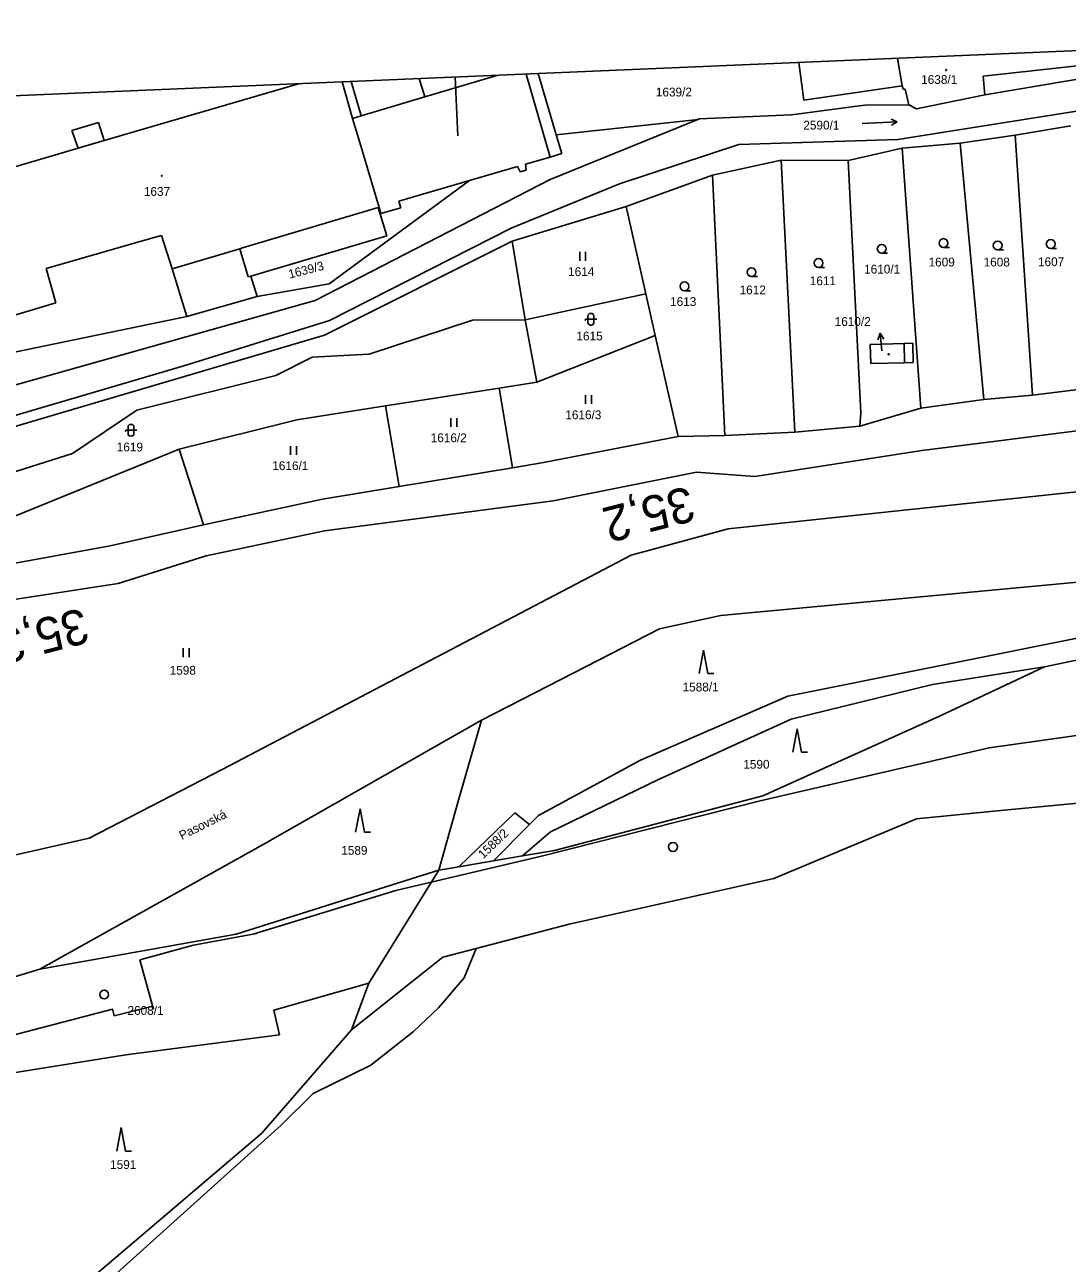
# Model space of a CAD drawing. Extents: x -806456 to -805395, y -1150847 to -1150506.
# Drawn here: x -806109.9 to -805932.5, y -1150734.5 to -1150523.9 of the extents above; entities that cross this region are included whole.
import ezdxf

# ---------------------------------------------------------------- set-up
doc = ezdxf.new("R2010")
doc.units = 0
for name, color, linetype in [('Default', 7, 'Continuous'), ('formát', 7, 'Continuous'), ('kilometráž - vrstava 7', 7, 'Continuous'), ('kn_celek - Cisla parcel pomocna', 7, 'Continuous'), ('kn_celek - Cisla pozemkovych parcel', 7, 'Continuous'), ('kn_celek - Cisla stavebnich parcel', 7, 'Continuous'), ('kn_celek - Dalsi prvky mapy popis', 7, 'Continuous'), ('kn_celek - Hranice parcel', 7, 'Continuous'), ('kn_celek - Vnitrni kresby', 7, 'Continuous'), ('kn_celek - Znacky budov', 7, 'Continuous'), ('kn_celek - Znacky kultur', 7, 'Continuous'), ('plochy - SZDC', 7, 'Continuous'), ('PSR_C2_2_trasa_Vimperk - Kabelová trasa', 7, 'Continuous')]:
    doc.layers.add(name, color=color, linetype=linetype)

# ---------------------------------------------------------------- blocks, each defined once
blk = doc.blocks.new('308')
at = {"layer": 'Default'}
for p, q in [((-7.5, 0.2), (0, 40.2)), ((0, 40.2), (7.5, 0.2)), ((7.5, 0.2), (17.5, 0.2))]:
    blk.add_line(p, q, dxfattribs=at)
blk = doc.blocks.new('306')
at = {"layer": 'Default'}
for p, q in [((-5.2, 0), (-5.2, 15)), ((4.8, 0), (4.8, 15))]:
    blk.add_line(p, q, dxfattribs=at)
blk = doc.blocks.new('304')
at = {"layer": 'Default'}
blk.add_line((-0.1, 0), (9.9, 0), dxfattribs=at)
blk.add_circle((-0.1, 7.5), 7.5, dxfattribs=at)
blk = doc.blocks.new('316')
at = {"layer": 'Default'}
for p, q in [((-8.3, 10), (-10, 8.1)), ((-5, 10), (-8.3, 10)), ((-5, 15.5), (-5, 4.5)), ((-5, 10), (5, 10)), ((0.5, 20), (-0.5, 20)), ((-0.5, 0), (0.5, 0)), ((5, 4.5), (5, 15.5)), ((10, 10), (5, 10))]:
    blk.add_line(p, q, dxfattribs=at)
for centre, start, end in [((-0.5, 15.5), 90, 180), ((-0.5, 4.5), 180, 270), ((0.5, 15.5), 0, 90), ((0.5, 4.5), 270, 0)]:
    blk.add_arc(centre, 4.5, start, end, dxfattribs=at)
blk = doc.blocks.new('402')
at = {"layer": 'Default'}
for p, q in [((-0.8, 0.8), (0.7, 0.8)), ((-0.8, 0.8), (-0.8, -0.7)), ((0.7, 0.8), (0.7, -0.7)), ((0.7, -0.7), (-0.8, -0.7))]:
    blk.add_line(p, q, dxfattribs=at)
blk = doc.blocks.new('Z61')
at = {"layer": 'Default'}
for p, q in [((0, 0), (30, 0)), ((30, 0), (19.2, 5.3)), ((30, 0), (19.2, -5.3))]:
    blk.add_line(p, q, dxfattribs=at)
blk = doc.blocks.new('802')
at = {"layer": 'Default'}
for p, q in [((-30, 0), (30, 0)), ((20, 5), (30, 0)), ((30, 0), (20, -5))]:
    blk.add_line(p, q, dxfattribs=at)

msp = doc.modelspace()

# ---------------------------------------------------------------- linework, layer by layer
at = {"layer": 'formát'}
for p, q in [((-805826.83, -1150523.88), (-806456.26, -1150550.6)), ((-806036.64, -1150532.78), (-806036.21, -1150542.77))]:
    msp.add_line(p, q, dxfattribs=at)
at = {"layer": 'kilometráž - vrstava 7'}
for centre in [(-805999.58, -1150663.73), (-806096.38, -1150688.84)]:
    msp.add_circle(centre, 0.75, dxfattribs=at)
at = {"layer": 'kn_celek - Hranice parcel'}
for p, q in [((-805977.29, -1150536.72), (-805978.14, -1150530.3)), ((-805946.48, -1150535.78), (-805914.7, -1150530.39)), ((-806041.82, -1150536.14), (-806029.54, -1150532.48)), ((-806022.54, -1150532.18), (-806019.46, -1150542.59)), ((-806063.28, -1150533.91), (-806096.37, -1150543.56)), ((-806042.75, -1150533.04), (-806041.82, -1150536.14)), ((-805977.29, -1150536.72), (-805960.6, -1150534.25)), ((-805960.6, -1150534.25), (-805960.43, -1150534.83)), ((-805960.43, -1150534.83), (-805960.05, -1150534.84)), ((-805960.05, -1150534.84), (-805959.42, -1150537.5)), ((-805958.14, -1150538.16), (-805946.48, -1150535.78)), ((-805978.52, -1150539.1), (-805967.87, -1150537.65)), ((-805967.87, -1150537.65), (-805966.95, -1150537.56)), ((-805966.95, -1150537.56), (-805959.42, -1150537.5)), ((-805959.42, -1150537.5), (-805958.14, -1150538.16)), ((-806097.35, -1150540.5), (-806101.91, -1150541.84)), ((-806096.37, -1150543.56), (-806097.35, -1150540.5)), ((-805995.79, -1150540.03), (-806019.46, -1150542.59)), ((-805995.08, -1150539.89), (-805995.79, -1150540.03)), ((-805995.08, -1150539.89), (-805979.47, -1150539.21)), ((-805979.47, -1150539.21), (-805978.52, -1150539.1)), ((-805941.33, -1150542.63), (-805931.86, -1150541.09)), ((-806100.8, -1150544.86), (-806101.91, -1150541.84)), ((-806019.46, -1150542.59), (-806018.51, -1150545.8)), ((-805950.71, -1150544.04), (-805941.33, -1150542.63)), ((-805941.33, -1150542.63), (-805938.4, -1150586.88)), ((-806114.14, -1150548.78), (-806100.8, -1150544.86)), ((-805969.76, -1150546.96), (-805960.55, -1150544.86)), ((-805960.55, -1150544.86), (-805950.71, -1150544.04)), ((-805960.55, -1150544.86), (-805957.42, -1150589.07)), ((-805950.71, -1150544.04), (-805946.65, -1150587.64)), ((-806020.5, -1150546.37), (-806024.69, -1150547.58)), ((-806018.51, -1150545.8), (-806020.5, -1150546.37)), ((-805992.86, -1150549.46), (-805981.18, -1150546.9)), ((-805981.18, -1150546.9), (-805969.76, -1150546.96)), ((-805981.18, -1150546.9), (-805978.86, -1150593.2)), ((-805967.59, -1150589.89), (-805969.76, -1150546.96)), ((-806026.01, -1150547.98), (-806034.23, -1150550.39)), ((-806025.58, -1150548.89), (-806026.01, -1150547.98)), ((-806024.56, -1150548.59), (-806025.58, -1150548.89)), ((-806024.69, -1150547.58), (-806024.56, -1150548.59)), ((-806007.57, -1150554.77), (-805992.86, -1150549.46)), ((-805992.86, -1150549.46), (-805990.76, -1150593.74)), ((-806058.11, -1150567.96), (-806034.23, -1150550.39)), ((-806034.23, -1150550.39), (-806046.24, -1150553.91)), ((-806049.73, -1150554.98), (-806049.6, -1150554.94)), ((-806049.73, -1150554.98), (-806048.3, -1150559.8)), ((-806049.6, -1150554.94), (-806049.29, -1150556)), ((-806049.29, -1150556), (-806045.9, -1150555.02)), ((-806045.9, -1150555.02), (-806046.24, -1150553.91)), ((-806007.57, -1150554.77), (-806026.96, -1150560.67)), ((-806004.21, -1150569.63), (-806007.57, -1150554.77)), ((-806088.1, -1150560.13), (-806086.61, -1150559.7)), ((-806086.61, -1150559.7), (-806084.82, -1150565.38)), ((-806071.41, -1150566.62), (-806048.3, -1150559.8)), ((-806106.27, -1150565.35), (-806088.1, -1150560.13)), ((-806058.91, -1150576.7), (-806026.96, -1150560.67)), ((-806026.96, -1150560.67), (-806024.74, -1150574.06)), ((-806104.61, -1150571.2), (-806106.27, -1150565.35)), ((-806084.82, -1150565.38), (-806082.33, -1150573.48)), ((-806071.41, -1150566.62), (-806070.37, -1150570.09)), ((-806070.37, -1150570.09), (-806058.11, -1150567.96)), ((-806082.33, -1150573.48), (-806070.37, -1150570.09)), ((-806024.74, -1150574.06), (-806004.21, -1150569.63)), ((-806002.61, -1150576.71), (-806004.21, -1150569.63)), ((-806119.82, -1150575.72), (-806104.61, -1150571.2)), ((-806140.34, -1150585.49), (-806082.33, -1150573.48)), ((-806033.68, -1150574.14), (-806051.26, -1150579.89)), ((-806024.74, -1150574.06), (-806033.68, -1150574.14)), ((-806024.74, -1150574.06), (-806022.77, -1150584.69)), ((-806115.37, -1150593.3), (-806058.91, -1150576.7)), ((-806022.77, -1150584.69), (-806002.61, -1150576.71)), ((-805998.72, -1150593.9), (-806002.61, -1150576.71)), ((-805966.01, -1150578.24), (-805960.25, -1150578.09)), ((-805965.92, -1150581.52), (-805966.01, -1150578.24)), ((-805960.25, -1150578.09), (-805958.74, -1150578.04)), ((-805958.74, -1150578.04), (-805958.71, -1150581.32)), ((-806060.99, -1150580.41), (-806067.16, -1150583.54)), ((-806051.26, -1150579.89), (-806060.99, -1150580.41)), ((-805960.16, -1150581.36), (-805965.92, -1150581.52)), ((-805958.71, -1150581.32), (-805960.16, -1150581.36)), ((-806067.16, -1150583.54), (-806090.84, -1150589.43)), ((-806029.15, -1150585.69), (-806022.77, -1150584.69)), ((-806048.5, -1150588.71), (-806029.15, -1150585.69)), ((-806029.15, -1150585.69), (-806027.42, -1150596.15)), ((-805938.4, -1150586.88), (-805946.65, -1150587.64)), ((-805927.83, -1150585.59), (-805938.4, -1150586.88)), ((-806090.84, -1150589.43), (-806101.77, -1150596.83)), ((-806063.57, -1150591.06), (-806048.5, -1150588.71)), ((-806046.18, -1150602.41), (-806048.5, -1150588.71)), ((-805957.42, -1150589.07), (-805967.77, -1150592.14)), ((-805946.65, -1150587.64), (-805957.42, -1150589.07)), ((-806083.6, -1150596.08), (-806063.57, -1150591.06)), ((-805967.77, -1150592.14), (-805967.59, -1150589.89)), ((-805990.76, -1150593.74), (-805998.72, -1150593.9)), ((-805978.86, -1150593.2), (-805990.76, -1150593.74)), ((-805978.86, -1150593.2), (-805967.77, -1150592.14)), ((-805930.82, -1150592.93), (-805944.13, -1150594.65)), ((-806021.64, -1150598.35), (-805998.72, -1150593.9)), ((-805944.13, -1150594.65), (-805957.21, -1150596.28)), ((-806118.38, -1150602.03), (-806101.77, -1150596.83)), ((-806116.57, -1150609.49), (-806083.6, -1150596.08)), ((-806083.6, -1150596.08), (-806079.49, -1150608.96)), ((-806027.42, -1150596.15), (-806026.91, -1150599.22)), ((-805957.21, -1150596.28), (-805985.67, -1150600.72)), ((-806026.91, -1150599.22), (-806046.18, -1150602.41)), ((-806026.91, -1150599.22), (-806021.64, -1150598.35)), ((-805995.57, -1150599.97), (-806019.97, -1150604.84)), ((-805985.67, -1150600.72), (-805995.57, -1150599.97)), ((-805990.21, -1150609.59), (-805890.43, -1150599.04)), ((-806059.25, -1150604.57), (-806046.18, -1150602.41)), ((-806079.49, -1150608.96), (-806059.25, -1150604.57)), ((-806019.97, -1150604.84), (-806058.89, -1150609.96)), ((-806095.36, -1150612.49), (-806079.49, -1150608.96)), ((-806058.89, -1150609.96), (-806079.02, -1150614.23)), ((-805990.21, -1150609.59), (-806006.71, -1150614.09)), ((-806120.89, -1150617.2), (-806095.36, -1150612.49)), ((-806094.01, -1150618.9), (-806079.02, -1150614.23)), ((-806006.71, -1150614.09), (-806076.28, -1150650.56)), ((-805991.42, -1150624.34), (-805889.59, -1150614.88)), ((-806094.01, -1150618.9), (-806120.22, -1150622.93)), ((-805955.67, -1150633.22), (-805906.01, -1150623.2)), ((-806001.85, -1150626.61), (-805991.42, -1150624.34)), ((-806018.57, -1150635.19), (-806001.85, -1150626.61)), ((-805936.34, -1150633.1), (-805905.92, -1150626.68)), ((-805955.67, -1150633.22), (-805980.05, -1150638.11)), ((-805955.42, -1150636.11), (-805936.34, -1150633.1)), ((-805954.21, -1150641.47), (-805936.34, -1150633.1)), ((-806032.16, -1150642.17), (-806018.57, -1150635.19)), ((-805979.44, -1150641.98), (-805955.42, -1150636.11)), ((-806005.08, -1150648.95), (-805980.05, -1150638.11)), ((-806069.3, -1150663.29), (-806032.16, -1150642.17)), ((-806036.17, -1150656.19), (-806032.16, -1150642.17)), ((-806002.04, -1150652.23), (-805979.44, -1150641.98)), ((-805984.31, -1150655.05), (-805954.21, -1150641.47)), ((-806076.28, -1150650.56), (-806098.93, -1150662.23)), ((-806022.45, -1150658.38), (-806005.08, -1150648.95)), ((-806020.42, -1150661.14), (-806002.04, -1150652.23)), ((-805944.43, -1150657.58), (-805909.49, -1150654.26)), ((-806039.45, -1150667.69), (-806036.17, -1150656.19)), ((-806019.74, -1150664.32), (-805984.31, -1150655.05)), ((-806026.5, -1150657.92), (-806036.02, -1150667.1)), ((-806023.99, -1150659.92), (-806026.5, -1150657.92)), ((-806023.99, -1150659.92), (-806022.45, -1150658.38)), ((-805982.42, -1150669.1), (-805958.14, -1150658.97)), ((-805958.14, -1150658.97), (-805944.43, -1150657.58)), ((-806030.13, -1150666.09), (-806023.99, -1150659.92)), ((-806020.42, -1150661.14), (-806025.19, -1150665.25)), ((-806098.93, -1150662.23), (-806129.77, -1150669.25)), ((-806107.35, -1150684.54), (-806069.3, -1150663.29)), ((-806030.13, -1150666.09), (-806025.19, -1150665.25)), ((-806025.19, -1150665.25), (-806019.74, -1150664.32)), ((-806039.45, -1150667.69), (-806036.02, -1150667.1)), ((-806036.02, -1150667.1), (-806030.13, -1150666.09)), ((-806073.91, -1150678.57), (-806043.04, -1150668.82)), ((-806051.33, -1150686.88), (-806039.45, -1150667.69)), ((-806043.04, -1150668.82), (-806039.45, -1150667.69)), ((-806017.22, -1150676.88), (-805982.42, -1150669.1)), ((-806033.08, -1150681), (-806017.22, -1150676.88)), ((-806096.14, -1150682.54), (-806073.91, -1150678.57)), ((-806038.72, -1150682.46), (-806033.08, -1150681)), ((-806035.11, -1150686.02), (-806033.08, -1150681)), ((-806107.35, -1150684.54), (-806096.14, -1150682.54)), ((-806054.27, -1150694.84), (-806038.72, -1150682.46)), ((-806152.11, -1150697.83), (-806107.35, -1150684.54)), ((-806035.11, -1150686.02), (-806039.5, -1150691.07)), ((-806067.49, -1150691.49), (-806051.33, -1150686.88)), ((-806051.33, -1150686.88), (-806054.27, -1150694.84)), ((-806066.55, -1150695.68), (-806067.49, -1150691.49)), ((-806039.5, -1150691.07), (-806043.71, -1150695.1)), ((-806054.27, -1150694.84), (-806069.54, -1150712.39)), ((-806092.7, -1150699.08), (-806066.55, -1150695.68)), ((-806043.71, -1150695.1), (-806050.99, -1150700.84)), ((-806114.99, -1150702.66), (-806092.7, -1150699.08)), ((-806050.99, -1150700.84), (-806060.8, -1150705.65)), ((-806060.8, -1150705.65), (-806066.25, -1150711.08)), ((-806066.25, -1150711.08), (-806109.37, -1150749.85)), ((-806069.54, -1150712.39), (-806118.66, -1150754.19))]:
    msp.add_line(p, q, dxfattribs=at)
at = {"layer": 'kn_celek - Vnitrni kresby'}
for p, q in [((-805961.39, -1150529.59), (-805960.6, -1150534.25)), ((-805946.77, -1150532.62), (-805914.93, -1150529.1)), ((-806024.59, -1150532.27), (-806020.5, -1150546.37)), ((-805946.48, -1150535.78), (-805946.77, -1150532.62)), ((-806055.88, -1150533.6), (-806054.09, -1150539.83)), ((-806052.65, -1150539.37), (-806054.35, -1150533.53)), ((-806052.65, -1150539.37), (-806041.82, -1150536.14)), ((-805913.56, -1150535.79), (-805961.29, -1150543.38)), ((-806054.09, -1150539.83), (-806052.65, -1150539.37)), ((-806054.09, -1150539.83), (-806052.86, -1150543.93)), ((-805995.08, -1150539.89), (-806020.46, -1150550.22)), ((-806096.37, -1150543.56), (-806100.8, -1150544.86)), ((-806052.86, -1150543.93), (-806049.6, -1150554.94)), ((-805988.36, -1150544.24), (-806008.67, -1150550.93)), ((-805961.29, -1150543.38), (-805988.36, -1150544.24)), ((-806020.46, -1150550.22), (-806060.49, -1150570.78)), ((-806027.11, -1150558.49), (-806008.67, -1150550.93)), ((-806072.85, -1150561.83), (-806049.73, -1150554.98)), ((-806058.01, -1150574.18), (-806027.11, -1150558.49)), ((-806084.82, -1150565.38), (-806073.32, -1150561.97)), ((-806073.32, -1150561.97), (-806072.85, -1150561.83)), ((-806073.32, -1150561.97), (-806071.89, -1150566.76)), ((-806071.89, -1150566.76), (-806071.41, -1150566.62)), ((-806060.49, -1150570.78), (-806120.54, -1150587.67)), ((-806082.8, -1150581.88), (-806058.01, -1150574.18)), ((-805960.25, -1150578.09), (-805960.16, -1150581.36)), ((-806118.66, -1150592.4), (-806082.8, -1150581.88))]:
    msp.add_line(p, q, dxfattribs=at)
at = {"layer": 'plochy - SZDC'}
for p, q in [((-805905.92, -1150626.68), (-805936.34, -1150633.1)), ((-805936.34, -1150633.1), (-805954.21, -1150641.47)), ((-805954.21, -1150641.47), (-805984.31, -1150655.05)), ((-805944.43, -1150657.58), (-805909.49, -1150654.26)), ((-805984.31, -1150655.05), (-806019.74, -1150664.32)), ((-805982.42, -1150669.1), (-805958.14, -1150658.97)), ((-805958.14, -1150658.97), (-805944.43, -1150657.58)), ((-806025.19, -1150665.25), (-806030.13, -1150666.09)), ((-806019.74, -1150664.32), (-806025.19, -1150665.25)), ((-806036.02, -1150667.1), (-806039.45, -1150667.69)), ((-806030.13, -1150666.09), (-806036.02, -1150667.1)), ((-806043.04, -1150668.82), (-806073.91, -1150678.57)), ((-806051.33, -1150686.88), (-806039.45, -1150667.69)), ((-806039.45, -1150667.69), (-806051.33, -1150686.88)), ((-806039.45, -1150667.69), (-806043.04, -1150668.82)), ((-806017.22, -1150676.88), (-805982.42, -1150669.1)), ((-806033.08, -1150681), (-806017.22, -1150676.88)), ((-806073.91, -1150678.57), (-806096.14, -1150682.54)), ((-806038.72, -1150682.46), (-806033.08, -1150681)), ((-806096.14, -1150682.54), (-806107.35, -1150684.54)), ((-806054.27, -1150694.84), (-806038.72, -1150682.46)), ((-806107.35, -1150684.54), (-806152.11, -1150697.83)), ((-806067.49, -1150691.49), (-806051.33, -1150686.88)), ((-806051.33, -1150686.88), (-806054.27, -1150694.84)), ((-806066.55, -1150695.68), (-806067.49, -1150691.49)), ((-806092.7, -1150699.08), (-806066.55, -1150695.68)), ((-806114.99, -1150702.66), (-806092.7, -1150699.08))]:
    msp.add_line(p, q, dxfattribs=at)
at = {"layer": 'PSR_C2_2_trasa_Vimperk - Kabelová trasa'}
for p, q in [((-805925.76, -1150644.05), (-805945.75, -1150646.88)), ((-805984.72, -1150655.91), (-805945.75, -1150646.88)), ((-806021.98, -1150665.32), (-805984.72, -1150655.91)), ((-806088.19, -1150690.53), (-806090.32, -1150682.96)), ((-806088.19, -1150690.53), (-806087.98, -1150691.34))]:
    msp.add_line(p, q, dxfattribs=at)
for points in [[(-806070.84, -1150678.49), (-806046.76, -1150671.15), (-806021.98, -1150665.32)], [(-806090.32, -1150682.96), (-806081.2, -1150680.45), (-806070.48, -1150678.43)], [(-806165.37, -1150711.96), (-806160.98, -1150708.44), (-806114.54, -1150696.43), (-806094.98, -1150691.3), (-806094.7, -1150692.45)], [(-806094.7, -1150692.45), (-806088.12, -1150690.8)]]:
    msp.add_lwpolyline(points, dxfattribs=at)

# ---------------------------------------------------------------- block references
at = {"layer": 'kn_celek - Cisla parcel pomocna', "xscale": 0.1, "yscale": 0.10000000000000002, "rotation": 95.19435000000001}
msp.add_blockref('Z61', (-805964.02, -1150579.33), dxfattribs=at)
at = {"layer": 'kn_celek - Znacky budov', "xscale": 0.1, "yscale": 0.10000000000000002}
for p in [(-805953.08, -1150531.57), (-806086.56, -1150549.58), (-805962.87, -1150579.93)]:
    msp.add_blockref('402', p, dxfattribs=at)
at = {"layer": 'kn_celek - Znacky kultur', "xscale": 0.10000000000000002, "yscale": 0.10000000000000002, "rotation": 2.8179328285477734}
msp.add_blockref('802', (-805964.41, -1150540.55), dxfattribs=at)
at = {"layer": 'kn_celek - Znacky kultur', "xscale": 0.1, "yscale": 0.10000000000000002}
for name, p in [('304', (-805964.04, -1150562.74)), ('304', (-805953.52, -1150561.76)), ('304', (-805944.31, -1150562.17)), ('304', (-805935.28, -1150561.91)), ('306', (-806014.93, -1150564.02)), ('304', (-805974.79, -1150565.15)), ('304', (-805986.2, -1150566.71)), ('304', (-805997.61, -1150569.12)), ('316', (-806013.55, -1150574.97)), ('306', (-806013.94, -1150588.37)), ('306', (-806036.85, -1150592.28)), ('316', (-806091.82, -1150593.85)), ('306', (-806064.13, -1150597.03)), ('306', (-806082.42, -1150631.42)), ('308', (-805994.37, -1150634.26)), ('308', (-805978.44, -1150647.65)), ('308', (-806052.83, -1150661.26)), ('308', (-806093.5, -1150715.5))]:
    msp.add_blockref(name, p, dxfattribs=at)

# ---------------------------------------------------------------- texts
at = {"layer": 'kilometráž - vrstava 7'}
for s, p in [('35,2', (-805996.87, -1150602.28)), ('35,3', (-806100.01, -1150623))]:
    msp.add_text(s, height=6, rotation=194.6315, dxfattribs=at).set_placement(p)
at = {"layer": 'kn_celek - Cisla parcel pomocna'}
msp.add_text('1610/2', height=1.5, dxfattribs=at).set_placement((-805972.06, -1150575.1))
at = {"layer": 'kn_celek - Cisla pozemkovych parcel'}
for s, p in [('1639/2', (-806002.49, -1150536.07)), ('2590/1', (-805977.39, -1150541.7)), ('1609', (-805956.08, -1150564.99)), ('1608', (-805946.71, -1150564.99)), ('1607', (-805937.46, -1150564.94)), ('1614', (-806017.42, -1150566.62)), ('1610/1', (-805967.05, -1150566.19)), ('1612', (-805988.24, -1150569.73)), ('1611', (-805976.29, -1150568.17)), ('1613', (-806000.07, -1150571.72)), ('1615', (-806016.01, -1150577.57)), ('1616/3', (-806017.9, -1150590.97)), ('1616/2', (-806040.81, -1150594.88)), ('1619', (-806094.24, -1150596.45)), ('1616/1', (-806067.77, -1150599.63)), ('1598', (-806085.23, -1150634.43)), ('1588/1', (-805997.94, -1150637.28)), ('1590', (-805987.61, -1150650.42)), ('1589', (-806056.03, -1150665.06)), ('2608/1', (-806092.41, -1150692.29)), ('1591', (-806095.37, -1150718.51))]:
    msp.add_text(s, height=1.5, dxfattribs=at).set_placement(p)
for s, rotation, p in [('1639/3', 14.385, (-806064.81, -1150567.06)), ('1588/2', 43.9279, (-806031.87, -1150665.83))]:
    msp.add_text(s, height=1.5, rotation=rotation, dxfattribs=at).set_placement(p)
at = {"layer": 'kn_celek - Cisla stavebnich parcel'}
for s, height, p in [('1638/1', 1.5, (-805957.34, -1150533.95)), ('1637', 1.5, (-806089.62, -1150552.99)), ('1610/2', 0.1, (-805964.02, -1150579.3))]:
    msp.add_text(s, height=height, dxfattribs=at).set_placement(p)
at = {"layer": 'kn_celek - Dalsi prvky mapy popis'}
msp.add_text('Pasovská', height=1.5, rotation=26.3981, dxfattribs=at).set_placement((-806083.16, -1150662.55))

doc.saveas('drawing.dxf')
